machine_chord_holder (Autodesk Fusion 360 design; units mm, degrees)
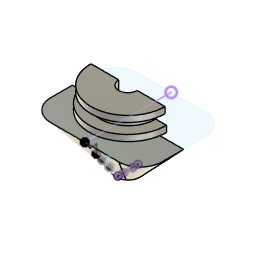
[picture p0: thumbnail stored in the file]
sketch "Sketch1" plane through (0, 0, 0) normal (0, 0, 1) x axis (1, 0, 0)
  circle C1 centre (0, 0) radius 3.75
  point P1 (0, 0)
  point P2 (0, 0)
  coincident P1 P2
  dimension "d1" diameter C1 = 7.5
work_plane "WorkPlane1" sketch "Sketch1" AlongDistance 15
sketch "Sketch2" plane through (0, 0, 15) normal (0, 0, 1) x axis (1, 0, 0)
  line L1 (11, 14) -> (-11, 14)
  line L2 (18, -7) -> (18, 7)
  line L3 (-11, -14) -> (11, -14)
  line L4 (-18, 7) -> (-18, -7)
  arc A1 centre (11, -7) radius 7 clockwise from (18, -7) to (11, -14)
  arc A2 centre (-11, -7) radius 7 clockwise from (-11, -14) to (-18, -7)
  arc A3 centre (-11, 7) radius 7 clockwise from (-18, 7) to (-11, 14)
  arc A4 centre (11, 7) radius 7 clockwise from (11, 14) to (18, 7)
  point P1 (0, 0)
  point P5 (0, 0)
  point P3 (18, -14)
  point P4 (-18, -14)
  point P2 (18, 14)
  horizontal L1
  perpendicular L1 L2
  parallel L1 L3
  parallel L2 L4
  coincident P1 P5
  coincident P3 L2
  coincident P3 L3
  tangent L2 A1
  tangent L3 A1
  coincident P4 L3
  coincident P4 L4
  tangent L3 A2
  tangent L4 A2
  equal A1 A2
  tangent L1 A3
  tangent L4 A3
  equal A1 A3
  coincident P2 L1
  coincident P2 L2
  tangent L1 A4
  tangent L2 A4
  equal A1 A4
  dimension "d3" distance P3 P4 = 36
  dimension "d4" distance P2 P3 = 28
  dimension "d5" radius A1 = 7
loft "Loft1" sketch "Sketch1" + "Sketch2"
sketch "Sketch3" plane through (0, 0, 15) normal (0, 0, 1) x axis (-1, 0, 0)
  curve K1 (-11, 14) -> (-11, 14)
  circle C1 centre (0, 0) radius 9
  point P1 (0, 0)
  point P4 (0, 0)
  coincident P1 P4
  dimension "d6" diameter C1 = 18
extrude "Extrude1" add sketch "Sketch3" profile of C1 along normal blind 2
sketch "Sketch4" plane through (0, 0, 17) normal (0, 0, 1) x axis (-1, 0, 0)
  circle C1 centre (0, 0) radius 9
  circle C2 centre (0, 0) radius 12.5
  point P1 (0, 0)
  point P3 (0, 0)
  coincident P1 P3
  dimension "d9" diameter C2 = 25
extrude "Extrude2" add sketch "Sketch4" along normal blind 2
sketch "Sketch5" plane through (0, 0, 0) normal (0, 0, -1) x axis (1, 0, 0)
  circle C1 centre (0, 0) radius 3.75
  circle C2 centre (0, 0) radius 2.75
  point P1 (0, 0)
  point P3 (0, 0)
  coincident P1 P3
  dimension "d12" diameter C2 = 5.5
extrude "Extrude3" cut sketch "Sketch5" profile of C2 against normal blind 25
fillet "Fillet1" radius 0.5
sketch "Sketch6" plane through (0, 0, 0) normal (1, 0, 0) x axis (0, 1, 0)
  line L1 (-3.0653, 0.1582) -> (-3.0555, 0.1576)
  curve K1 (-3.0555, 0.1576) -> (-1.1959, 0.1406)
  curve K2 (-1.1959, 0.1406) -> (1.6789, 0.1404)
  curve K3 (1.6789, 0.1404) -> (3.359, 0.1613)
  curve K4 (3.359, 0.1613) -> (3.0653, 0.1582)
  curve K5 (3.0653, 0.1582) -> (1.1959, 0.1406)
  curve K6 (1.1959, 0.1406) -> (-1.6789, 0.1404)
  curve K7 (-1.6789, 0.1404) -> (-3.359, 0.1613)
  curve K8 (-3.359, 0.1613) -> (-3.0653, 0.1582)
  line L2 (-14, 15) -> (-3.0653, 0.1582)
  line L3 (14, 15) -> (-14, 15)
  line L4 (-3.0653, 0.1582) -> (-14, 15)
  line L5 (-12.2205, 12.5847) -> (-14, 15)
  line L6 (-10.2205, 12.5847) -> (-12.2205, 12.5847)
  line L7 (-10.2205, 9.8701) -> (-10.2205, 12.5847)
  line L8 (-5.9276, 7.2976) -> (-8.3252, 7.2976)
  line L9 (-5.9276, 4.0432) -> (-5.9276, 7.2976)
  point P11 (-14, 15)
  point P13 (-14, 15)
  point P16 (-10.2205, 9.8701)
  point P17 (-8.3252, 7.2976)
  point P19 (-5.9276, 4.0432)
  point P14 (-12.2205, 12.5847)
  point P15 (-10.2205, 12.5847)
  coincident P11 P13
  parallel L4 L5
  horizontal L6
  coincident L2 P16
  perpendicular L6 L7
  coincident L2 P17
  horizontal L8
  coincident L2 P19
  perpendicular L8 L9
  dimension "d17" distance P13 P14 = 3
  dimension "d18" distance P14 P15 = 2
sketch "Sketch7" plane through (0, 0, 15) normal (0, 0, 1) x axis (-1, 0, 0)
  curve K1 (-11, 14) -> (-11, 14)
  circle C1 centre (0, 0) radius 9
sketch "Sketch8" plane through (0, 0, 0) normal (1, 0, 0) x axis (0, 1, 0)
work_plane "WorkPlane2" sketch "Sketch7" AlongDistance -7.702
sketch "Sketch9" plane through (0, 0, 7.298) normal (0, 0, 1) x axis (1, 0, 0)
sketch "Sketch10" plane through (0, 0, 7.298) normal (0, 0, 1) x axis (1, 0, 0)
split "Split1"
delete_face "DeleteFace2"
delete_face "DeleteFace3"
remove_body "RemoveBody1"
sketch "Sketch11" plane through (0, 0, 19) normal (0, 0, 1) x axis (-1, 0, 0)
  line L1 (-2.75, 0) -> (-12.5, 0)
  line L2 (12.5, 0) -> (2.75, 0)
  arc A1 centre (0, 0) radius 2.75 clockwise from (-2.75, 0) to (2.75, 0)
  arc A2 centre (0, 0) radius 12.5 clockwise from (-12.5, 0) to (12.5, 0)
  circle C1 centre (0, 0) radius 9
  circle C2 centre (0, 0) radius 2.75
  point P1 (0, 0)
  point P7 (0, 0)
  point P8 (0, 0)
  coincident P1 P7
  coincident P1 P8
  dimension "d20" diameter C1 = 18
  dimension "d21" diameter C2 = 5.5
extrude "Extrude4" add sketch "Sketch11" profile of L1 A1 L2 C1 C2 along normal blind 3
sketch "Sketch12" plane through (0, 0, 22) normal (0, 0, 1) x axis (-1, 0, 0)
  line L1 (-2.75, 0) -> (-9, 0)
  line L2 (9, 0) -> (2.75, 0)
  line L3 (-12, 0) -> (-9, 0)
  line L4 (12, 0) -> (9, 0)
  arc A1 centre (0, 0) radius 9 clockwise from (-9, 0) to (9, 0)
  arc A2 centre (0, 0) radius 2.75 clockwise from (-2.75, 0) to (2.75, 0)
  circle C1 centre (0, 0) radius 12
  circle C2 centre (0, 0) radius 2.75
  point P1 (0, 0)
  point P7 (0, 0)
  point P3 (-9, 0)
  point P9 (-9, 0)
  point P10 (-12, 0)
  point P2 (9, 0)
  point P11 (9, 0)
  point P12 (12, 0)
  coincident P1 P7
  concentric C1 C2
  coincident P3 P9
  coincident C1 P10
  parallel L1 L3
  coincident P2 P11
  coincident C1 P12
  parallel L2 L4
  dimension "d24" diameter C1 = 24
  dimension "d25" diameter C2 = 5.5
extrude "Extrude5" add sketch "Sketch12" along normal blind 2
sketch "Sketch13" plane through (0, 0, 24) normal (0, 0, 1) x axis (-1, 0, 0)
  line L1 (12, 0) -> (2.75, 0)
  line L2 (-2.75, 0) -> (-12, 0)
  arc A1 centre (0, 0) radius 12 clockwise from (-12, 0) to (12, 0)
  arc A2 centre (0, 0) radius 2.75 clockwise from (-2.75, 0) to (2.75, 0)
  circle C1 centre (0, 0) radius 3
  point P1 (0, 0)
  point P7 (0, 0)
  coincident P1 P7
  dimension "d28" diameter C1 = 6
extrude "Extrude6" cut sketch "Sketch13" profile of L1 L2 A2 C1 against normal blind 35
